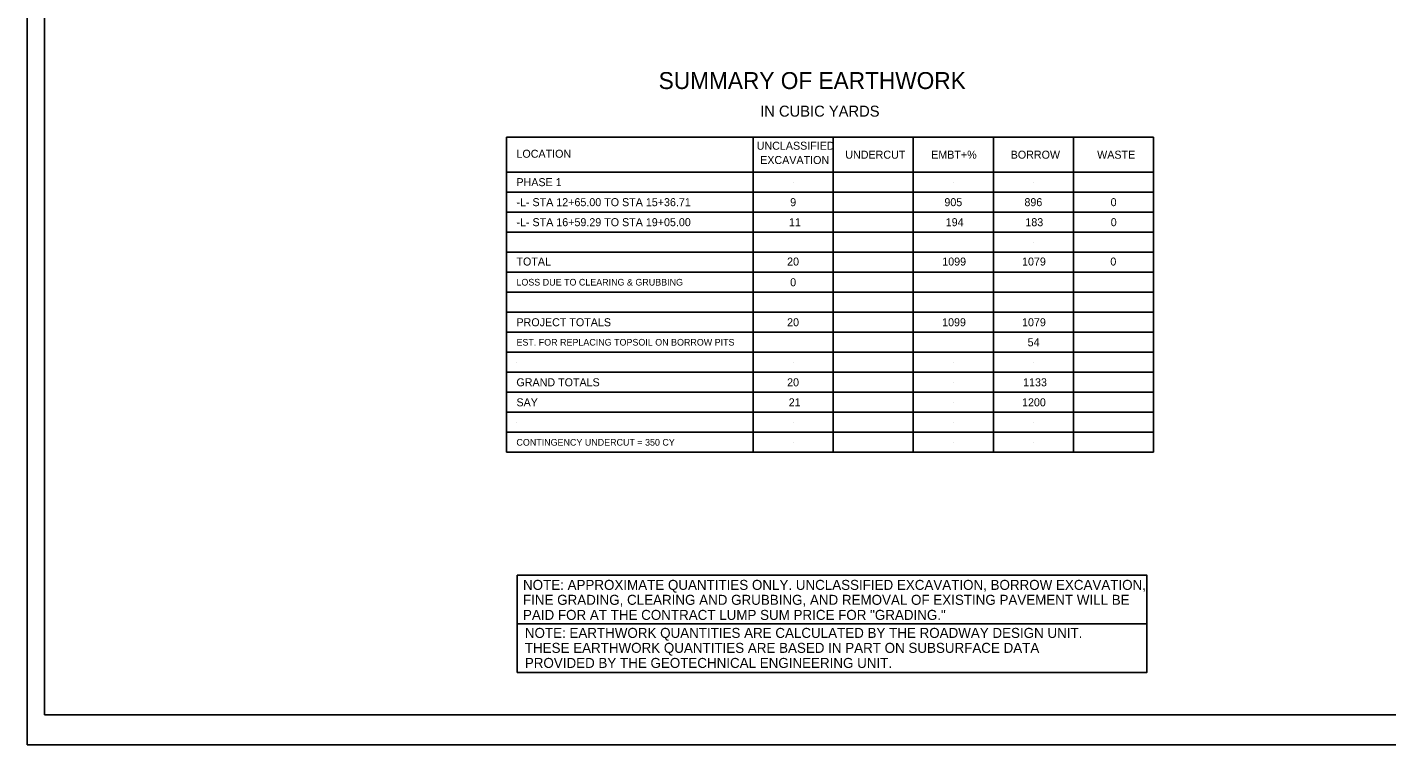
# Model space of a CAD drawing. Extents: x 578158 to 582505, y -54320 to -53220.
# Drawn here: x 578158 to 579178, y -54320 to -53782 of the extents above; entities that cross this region are included whole.
import ezdxf

# ---------------------------------------------------------------- set-up
doc = ezdxf.new("R2010")
doc.units = 0
for name, color, linetype in [('Old_Level_41', 7, 'Continuous'), ('Sheet Plot Border Inside CELL', 7, 'Continuous'), ('Sheet Plot Border Outside CELL', 7, 'Continuous')]:
    doc.layers.add(name, color=color, linetype=linetype)

msp = doc.modelspace()

# ---------------------------------------------------------------- linework, layer by layer
at = {"layer": 'Old_Level_41'}
for p, q in [((578517.7, -53890.4), (579002.7, -53890.4)), ((579002.7, -53905.4), (578517.7, -53905.4)), ((578517.7, -53905.4), (579002.7, -53905.4)), ((578517.7, -53905.4), (579002.7, -53905.4)), ((578525.2, -53897.9), (578525.2, -53897.9)), ((578732.7, -53897.9), (578732.7, -53897.9)), ((578852.7, -53897.9), (578852.7, -53897.9)), ((578852.8, -53897.9), (578852.8, -53897.9)), ((578912.8, -53897.9), (578912.8, -53897.9)), ((578525.2, -53912.9), (578525.2, -53912.9)), ((578732.7, -53912.9), (578732.7, -53912.9)), ((578852.7, -53912.9), (578852.7, -53912.9)), ((578852.8, -53912.9), (578852.8, -53912.9)), ((578912.8, -53912.9), (578912.8, -53912.9)), ((579002.7, -53920.4), (578517.7, -53920.4)), ((579002.7, -53935.4), (578517.7, -53935.4)), ((578525.2, -53927.9), (578525.2, -53927.9)), ((578732.7, -53927.9), (578732.7, -53927.9)), ((578732.7, -53927.9), (578732.7, -53927.9)), ((578852.7, -53927.9), (578852.7, -53927.9)), ((578852.8, -53927.9), (578852.8, -53927.9)), ((578912.8, -53927.9), (578912.8, -53927.9)), ((578912.8, -53927.9), (578912.8, -53927.9)), ((578912.8, -53942.9), (578912.8, -53942.9)), ((578912.8, -53942.9), (578912.8, -53942.9)), ((579002.7, -53950.4), (578517.7, -53950.4)), ((579002.7, -53965.4), (578517.7, -53965.4)), ((579002.7, -53980.4), (578517.7, -53980.4)), ((579002.7, -53995.4), (578517.7, -53995.4)), ((579002.7, -54010.4), (578517.7, -54010.4)), ((579002.7, -54025.4), (578517.7, -54025.4)), ((578525.2, -54032.9), (578525.2, -54032.9)), ((578732.7, -54032.9), (578732.7, -54032.9)), ((578732.7, -54032.9), (578732.7, -54032.9)), ((578852.7, -54032.9), (578852.7, -54032.9)), ((578852.8, -54032.9), (578852.8, -54032.9)), ((578912.8, -54032.9), (578912.8, -54032.9)), ((579002.7, -54040.4), (578517.7, -54040.4)), ((578525.2, -54047.9), (578525.2, -54047.9)), ((578732.7, -54047.9), (578732.7, -54047.9)), ((578852.7, -54047.9), (578852.7, -54047.9)), ((578852.8, -54047.9), (578852.8, -54047.9)), ((578912.8, -54047.9), (578912.8, -54047.9)), ((579002.7, -54055.4), (578517.7, -54055.4)), ((578525.2, -54062.9), (578525.2, -54062.9)), ((578525.2, -54062.9), (578525.2, -54062.9)), ((578525.2, -54062.9), (578525.2, -54062.9)), ((578732.7, -54062.9), (578732.7, -54062.9)), ((578732.7, -54062.9), (578732.7, -54062.9)), ((578852.7, -54062.9), (578852.7, -54062.9)), ((578852.7, -54062.9), (578852.7, -54062.9)), ((578852.8, -54062.9), (578852.8, -54062.9)), ((578852.8, -54062.9), (578852.8, -54062.9)), ((578912.8, -54062.9), (578912.8, -54062.9)), ((578912.8, -54062.9), (578912.8, -54062.9)), ((578912.8, -54062.9), (578912.8, -54062.9)), ((579002.7, -54070.4), (578517.7, -54070.4)), ((579002.7, -54070.4), (578517.7, -54070.4)), ((578525.2, -54077.9), (578525.2, -54077.9)), ((578525.2, -54077.9), (578525.2, -54077.9)), ((578732.7, -54077.9), (578732.7, -54077.9)), ((578732.7, -54077.9), (578732.7, -54077.9)), ((578852.7, -54077.9), (578852.7, -54077.9)), ((578852.7, -54077.9), (578852.7, -54077.9)), ((578852.8, -54077.9), (578852.8, -54077.9)), ((578852.8, -54077.9), (578852.8, -54077.9)), ((578912.8, -54077.9), (578912.8, -54077.9)), ((578912.8, -54077.9), (578912.8, -54077.9)), ((578912.8, -54077.9), (578912.8, -54077.9)), ((579002.7, -54085.4), (578517.7, -54085.4)), ((578525.2, -54092.9), (578525.2, -54092.9)), ((578525.2, -54092.9), (578525.2, -54092.9)), ((578525.2, -54092.9), (578525.2, -54092.9)), ((578732.7, -54092.9), (578732.7, -54092.9)), ((578732.7, -54092.9), (578732.7, -54092.9)), ((578852.7, -54092.9), (578852.7, -54092.9)), ((578852.7, -54092.9), (578852.7, -54092.9)), ((578852.7, -54092.9), (578852.7, -54092.9)), ((578852.8, -54092.9), (578852.8, -54092.9)), ((578852.8, -54092.9), (578852.8, -54092.9)), ((578852.8, -54092.9), (578852.8, -54092.9)), ((578912.8, -54092.9), (578912.8, -54092.9)), ((578912.8, -54092.9), (578912.8, -54092.9)), ((578912.8, -54092.9), (578912.8, -54092.9)), ((579002.7, -54100.4), (578517.7, -54100.4)), ((579002.7, -54100.4), (578517.7, -54100.4))]:
    msp.add_line(p, q, dxfattribs=at)
for points in [[(578517.7, -54100.4), (578517.7, -53864.2)], [(578517.7, -53864.2), (579002.7, -53864.2)], [(578702.7, -54100.4), (578702.7, -53864.2)], [(578762.7, -53864.2), (578762.7, -54100.4)], [(578822.7, -53864.2), (578822.7, -54100.4)], [(578882.7, -53864.2), (578882.7, -54100.4)], [(578882.7, -53864.2), (578882.7, -54100.4)], [(578942.7, -53864.2), (578942.7, -54100.4)], [(579002.7, -53864.2), (579002.7, -54100.4)], [(579002.7, -53890.4), (578517.7, -53890.4)], [(579002.7, -53905.4), (578517.7, -53905.4)], [(578762.7, -54100.4), (578762.7, -53905.4)], [(578822.7, -54100.4), (578822.7, -53905.4)], [(578882.7, -54100.4), (578882.7, -53905.4)], [(578882.7, -54100.4), (578882.7, -53905.4)], [(578942.7, -54100.4), (578942.7, -53905.4)], [(579002.7, -54100.4), (579002.7, -53905.4)]]:
    msp.add_lwpolyline(points, dxfattribs=at)
for points in [[(578525.8, -54192.5), (578997.8, -54192.5), (578997.8, -54229), (578525.8, -54229)], [(578525.8, -54229), (578997.8, -54229), (578997.8, -54265.4), (578525.8, -54265.4)]]:
    msp.add_lwpolyline(points, close=True, dxfattribs=at)
at = {"layer": 'Sheet Plot Border Inside CELL'}
msp.add_lwpolyline([(578171.4, -54297.1), (579837.4, -54297.1), (579837.4, -53242.1), (578171.4, -53242.1)], close=True, dxfattribs=at)
at = {"layer": 'Sheet Plot Border Outside CELL'}
msp.add_lwpolyline([(578158.4, -54319.6), (579841.9, -54319.6), (579841.9, -53219.6), (578158.4, -53219.6)], close=True, dxfattribs=at)

# ---------------------------------------------------------------- texts
at = {"layer": 'Old_Level_41'}
for s, height, p in [('SUMMARY OF EARTHWORK', 12.7, (578631.8, -53828.1)), ('LOCATION', 6, (578525.2, -53879.6)), ('UNCLASSIFIED', 6, (578705.3, -53873.6)), ('UNDERCUT', 6, (578771.7, -53880.3)), ('EMBT+%', 6, (578836.1, -53880.3)), ('BORROW', 6, (578895.7, -53880.3)), ('WASTE', 6, (578960.5, -53880.3)), ('EXCAVATION', 6, (578707.9, -53884.3)), ('PHASE 1', 6, (578525.2, -53900.9)), ('-L- STA 12+65.00 TO STA 15+36.71', 6, (578525.2, -53915.9)), ('9', 6, (578730.4, -53915.9)), ('905', 6, (578846, -53915.9)), ('896', 6, (578906, -53915.9)), ('0', 6, (578970.6, -53915.9)), ('-L- STA 16+59.29 TO STA 19+05.00', 6, (578525.2, -53930.9)), ('11', 6, (578729.5, -53930.9)), ('194', 6, (578847, -53930.9)), ('183', 6, (578906.7, -53930.9)), ('0', 6, (578970.7, -53930.9)), ('TOTAL', 6, (578525.2, -53960.4)), ('20', 6, (578728.1, -53960.4)), ('1099', 6, (578844.4, -53960.4)), ('1079', 6, (578904.2, -53960.4)), ('0', 6, (578970.4, -53960.4)), ('LOSS DUE TO CLEARING & GRUBBING', 5, (578525.2, -53975.4)), ('0', 6, (578730.4, -53975.9)), ('PROJECT TOTALS', 6, (578525.2, -54005.9)), ('20', 6, (578728.1, -54005.9)), ('1099', 6, (578844.3, -54005.9)), ('1079', 6, (578904.2, -54005.9)), ('EST. FOR REPLACING TOPSOIL ON BORROW PITS', 5, (578525.2, -54020.4)), ('54', 6, (578908.4, -54020.9)), ('GRAND TOTALS', 6, (578525.2, -54050.9)), ('20', 6, (578728.1, -54050.9)), ('1133', 6, (578905, -54050.9)), ('SAY', 6, (578525.2, -54065.9)), ('21', 6, (578729.3, -54065.9)), ('1200', 6, (578904.2, -54065.9)), ('CONTINGENCY UNDERCUT = 350 CY', 5, (578525.2, -54095.4)), ('NOTE: APPROXIMATE QUANTITIES ONLY. UNCLASSIFIED EXCAVATION, BORROW EXCAVATION,', 7.5, (578530.1, -54203.5)), ('FINE GRADING, CLEARING AND GRUBBING, AND REMOVAL OF EXISTING PAVEMENT WILL BE', 7.5, (578530.1, -54214.7)), ('PAID FOR AT THE CONTRACT LUMP SUM PRICE FOR "GRADING."', 7.5, (578530.1, -54226)), ('NOTE: EARTHWORK QUANTITIES ARE CALCULATED BY THE ROADWAY DESIGN UNIT.', 7.5, (578531.5, -54239.5)), ('THESE EARTHWORK QUANTITIES ARE BASED IN PART ON SUBSURFACE DATA ', 7.5, (578531.5, -54250.7)), ('PROVIDED BY THE GEOTECHNICAL ENGINEERING UNIT.', 7.5, (578531.5, -54262))]:
    msp.add_text(s, height=height, dxfattribs=at).set_placement(p)
msp.add_text('IN CUBIC YARDS', height=8.25, rotation=360, dxfattribs=at).set_placement((578707.9, -53848.8))

doc.saveas('drawing.dxf')
